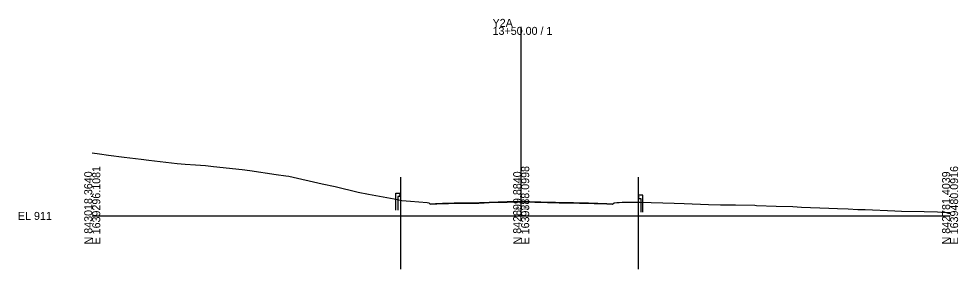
# Model space of a CAD drawing. Extents: x -26 to 303, y -10 to 10517.
# Drawn here: x -25.7 to 302.8, y 2981.3 to 3069.1 of the extents above; entities that cross this region are included whole.
import ezdxf

# ---------------------------------------------------------------- set-up
doc = ezdxf.new("R2010")
doc.units = 0
for name, color, linetype in [('Exist Cross Section Cell', 7, 'Continuous'), ('Exist XS Center Line Elevation Label', 7, 'Continuous'), ('Exist XS Ground Line', 7, 'Continuous'), ('Prop CMT Guardrail Widen Shoulder', 7, 'Continuous'), ('Prop CMT Pvmt Surface Overlay', 7, 'Continuous'), ('Scratch_Level_0', 7, 'Continuous')]:
    doc.layers.add(name, color=color, linetype=linetype)

msp = doc.modelspace()

# ---------------------------------------------------------------- linework, layer by layer
at = {"layer": 'Exist Cross Section Cell'}
for p, q in [((150, 3000), (150, 3066.25)), ((0, 3000), (150, 3000)), ((150, 3000), (300, 3000))]:
    msp.add_line(p, q, dxfattribs=at)
at = {"layer": 'Exist XS Ground Line'}
msp.add_lwpolyline([(0, 3022.08), (2.48, 3021.75), (5.65, 3021.34), (11.19, 3020.6), (17.08, 3019.88), (19.77, 3019.58), (29.74, 3018.38), (32.51, 3018.11), (36.08, 3017.91), (39.64, 3017.68), (42.4, 3017.36), (52.39, 3016.25), (55.06, 3015.89), (64.35, 3014.53), (67.72, 3014.05), (68.69, 3013.87), (80.38, 3011.23), (85, 3010.3), (93.04, 3008.36), (96.66, 3007.66), (105.63, 3005.95), (108.31, 3005.4), (111.27, 3005.14), (117.13, 3004.66), (117.73, 3004.61), (118.17, 3004.14), (120.08, 3004.23), (120.46, 3004.26), (122.52, 3004.34), (122.95, 3004.35), (124.55, 3004.38), (126.6, 3004.42), (128.11, 3004.44), (129.28, 3004.44), (130.68, 3004.47), (131.93, 3004.5), (133.05, 3004.5), (134.75, 3004.5), (135.24, 3004.51), (135.61, 3004.53), (137.02, 3004.62), (138.83, 3004.69), (141.94, 3004.77), (142.47, 3004.79), (143.01, 3004.8), (143.59, 3004.83), (145.11, 3004.87), (145.93, 3004.89), (146.98, 3004.91), (148.05, 3004.92), (148.79, 3004.93), (150, 3004.93), (151.44, 3004.91), (153.05, 3004.89), (154.83, 3004.85), (155.2, 3004.85), (156.88, 3004.81), (157.75, 3004.78), (159.21, 3004.73), (160.93, 3004.69), (161.96, 3004.67), (163.29, 3004.63), (163.74, 3004.61), (164.1, 3004.61), (166.9, 3004.56), (167.32, 3004.55), (168.25, 3004.53), (170.43, 3004.48), (171.44, 3004.46), (173.59, 3004.41), (175.52, 3004.34), (176.76, 3004.3), (179.95, 3004.23), (180.88, 3004.19), (181.96, 3004.13), (182.55, 3004.61), (183.48, 3004.65), (184.32, 3004.7), (185.3, 3004.76), (186.08, 3004.78), (189.49, 3004.86), (191.47, 3004.77), (203.56, 3004.51), (206.99, 3004.37), (215.46, 3004), (219.66, 3003.9), (224.95, 3003.9), (231.76, 3003.71), (232.32, 3003.7), (239.2, 3003.45), (244.98, 3003.27), (248.07, 3003.12), (257.64, 3002.66), (260.58, 3002.56), (264.38, 3002.43), (267.71, 3002.3), (270.3, 3002.19), (280.68, 3001.74), (282.96, 3001.66), (290.88, 3001.5), (295.62, 3001.4), (296.99, 3001.35), (300, 3001.17)], dxfattribs=at)
at = {"layer": 'Prop CMT Guardrail Widen Shoulder'}
for points in [[(106.17, 3002.01), (106.17, 3008.01)], [(106.17, 3008.01), (107.5, 3008.01), (107.77, 3007.72)], [(107.77, 3007.13), (107.5, 3006.84), (106.83, 3006.84)], [(106.83, 3006.84), (106.83, 3002.01)], [(107.77, 3007.72), (107.5, 3007.42)], [(107.5, 3007.42), (107.77, 3007.13)], [(192.56, 3007.29), (191.23, 3007.29), (190.96, 3007)], [(190.96, 3007), (191.23, 3006.71)], [(191.23, 3006.71), (190.96, 3006.42)], [(190.96, 3006.42), (191.23, 3006.13), (191.9, 3006.13)], [(191.9, 3006.13), (191.9, 3001.29)], [(192.56, 3001.29), (192.56, 3007.29)]]:
    msp.add_lwpolyline(points, dxfattribs=at)
at = {"layer": 'Prop CMT Pvmt Surface Overlay'}
msp.add_lwpolyline([(118.06, 3004.26), (120.08, 3004.36), (120.45, 3004.38), (122.52, 3004.47), (122.95, 3004.48), (124.54, 3004.51), (126.6, 3004.55), (128.11, 3004.56), (129.28, 3004.56), (130.67, 3004.59), (131.93, 3004.63), (133.05, 3004.63), (134.75, 3004.63), (135.23, 3004.63), (135.6, 3004.65), (137.01, 3004.75), (138.83, 3004.82), (141.94, 3004.9), (142.47, 3004.91), (143.01, 3004.93), (143.59, 3004.95), (145.1, 3005), (145.92, 3005.02), (146.98, 3005.03), (148.05, 3005.04), (148.79, 3005.06), (150, 3005.05), (151.44, 3005.04), (153.06, 3005.01), (154.84, 3004.98), (155.21, 3004.97), (156.89, 3004.93), (159.22, 3004.86), (160.93, 3004.81), (161.96, 3004.79), (163.29, 3004.75), (163.75, 3004.74), (164.1, 3004.73), (166.9, 3004.69), (167.32, 3004.68), (168.25, 3004.66), (170.43, 3004.61), (171.45, 3004.59), (173.6, 3004.53), (175.52, 3004.46), (176.76, 3004.43), (179.96, 3004.36), (182.11, 3004.25)], dxfattribs=at)
at = {"layer": 'Scratch_Level_0'}
for p, q in [((107.77, 3013.63), (107.77, 2981.3)), ((190.96, 3013.63), (190.96, 2981.3)), ((107.77, 3007.72), (107.77, 3005.51)), ((190.96, 3007), (190.96, 3004.79))]:
    msp.add_line(p, q, dxfattribs=at)

# ---------------------------------------------------------------- texts
at = {"layer": 'Exist Cross Section Cell'}
for s, p in [('Y2A', (140, 3066.25)), ('13+50.00 / 1', (140, 3063.45)), ('EL 911', (-26, 2998.6))]:
    msp.add_text(s, height=2.8, dxfattribs=at).set_placement(p)
for s, p in [('E 1639296.1081', (2.8, 2990)), ('E 1639388.0998', (152.8, 2990)), ('E 1639480.0916', (302.8, 2990)), ('N 843018.3640', (0, 2990)), ('N 842899.8840', (150, 2990)), ('N 842781.4039', (300, 2990))]:
    msp.add_text(s, height=2.8, rotation=90, dxfattribs=at).set_placement(p)
at = {"layer": 'Exist XS Center Line Elevation Label'}
msp.add_text('915.93', height=1, dxfattribs=at).set_placement((148.06, 3002.1))

doc.saveas('drawing.dxf')
